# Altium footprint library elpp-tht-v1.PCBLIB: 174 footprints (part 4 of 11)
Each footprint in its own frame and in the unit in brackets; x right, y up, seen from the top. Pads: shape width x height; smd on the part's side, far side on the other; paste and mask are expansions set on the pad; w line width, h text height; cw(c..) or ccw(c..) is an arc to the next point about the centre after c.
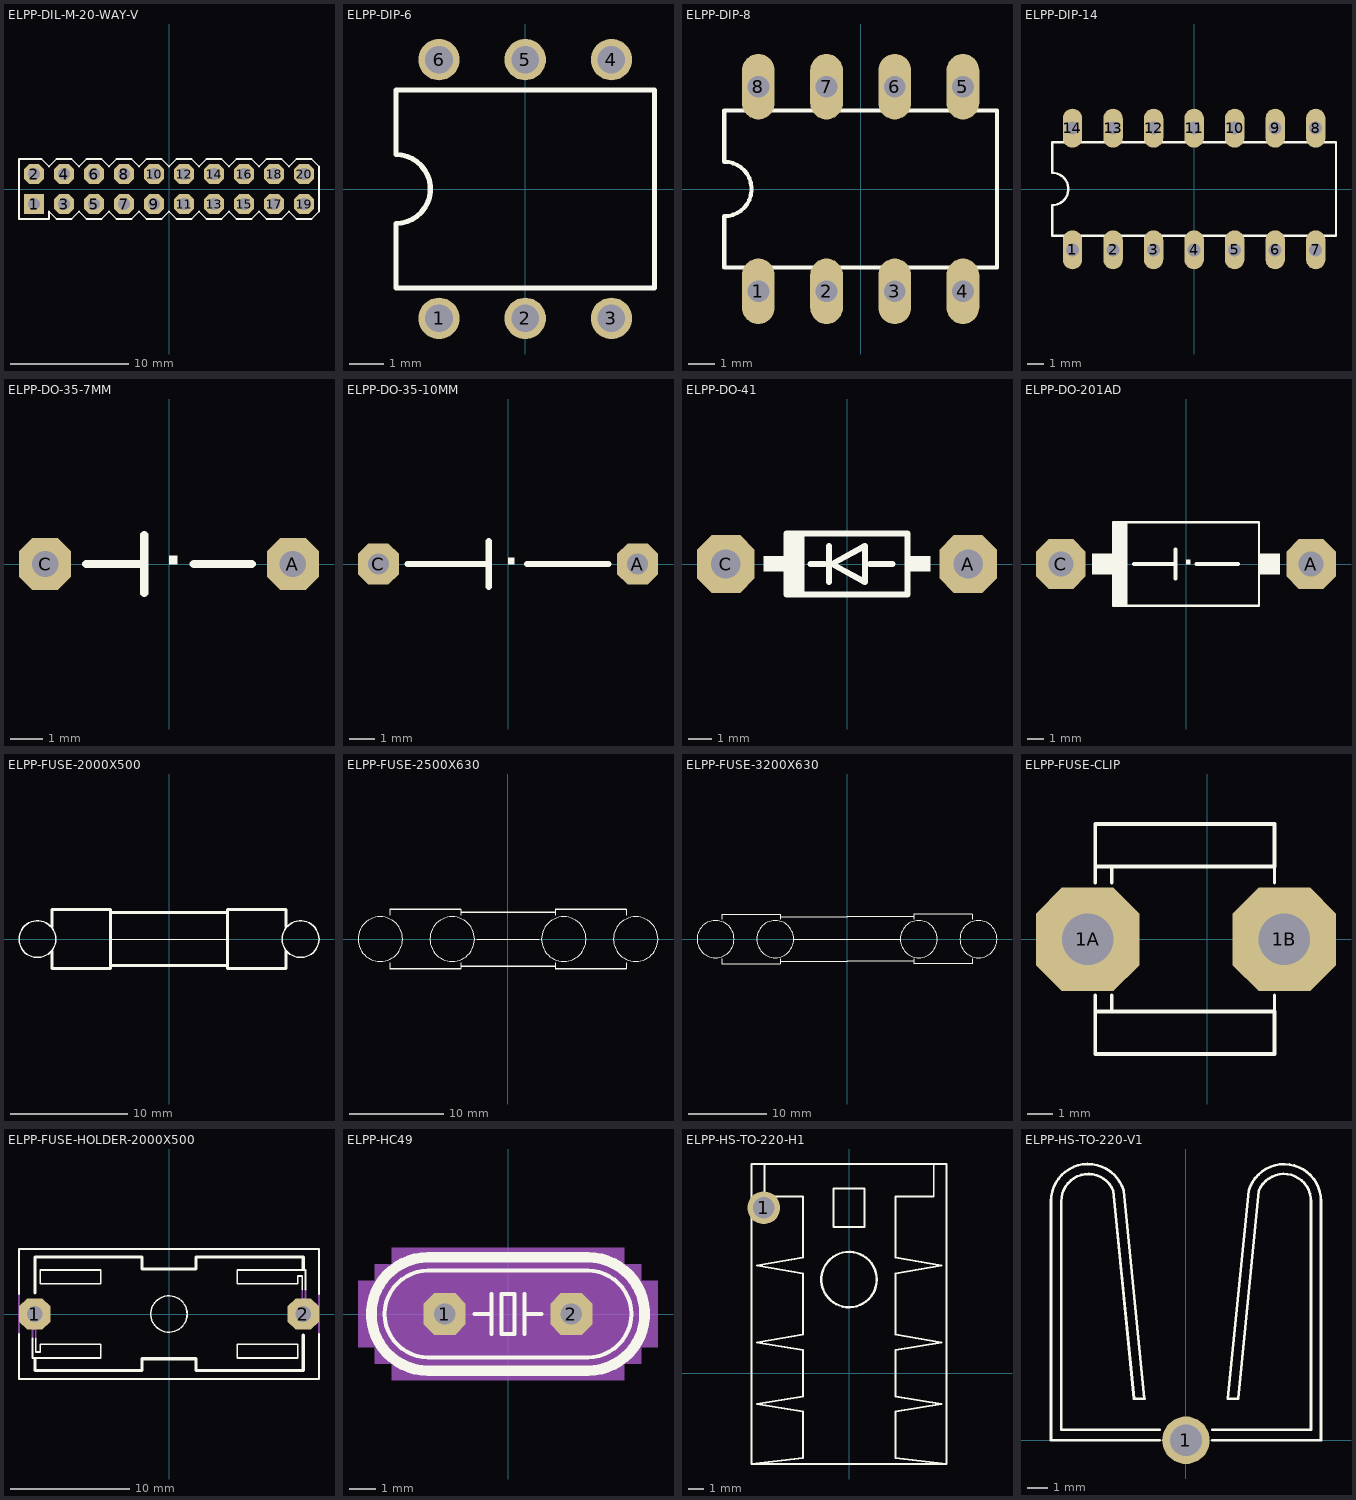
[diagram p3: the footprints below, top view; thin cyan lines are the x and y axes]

## ELPP-DIL-M-20-WAY-V [mil]
pads (20):
  rect 67x67 hole 40: 1(-450,-50)
  oct 67x67 hole 40: 2(-450,50) 3(-350,-50) 4(-350,50) 5(-250,-50) 6(-250,50) 7(-150,-50) 8(-150,50) 9(-50,-50) 10(-50,50) 11(50,-50) 12(50,50) 13(150,-50) 14(150,50) 15(250,-50) 16(250,50) 17(350,-50) 18(350,50) 19(450,-50) 20(450,50)
Top Overlay:
  lines w6: -500,-100 -400,-100 -400,-75 -375,-100 -325,-100 -300,-75 -275,-100 -225,-100 -200,-75 -175,-100 -125,-100 -100,-75 -75,-100 -25,-100 0,-75 25,-100 75,-100 100,-75 125,-100 175,-100 200,-75 225,-100 275,-100 300,-75 325,-100 375,-100 400,-75 425,-100 475,-100 500,-75 500,75 475,100 425,100 400,75 375,100 325,100 300,75 275,100 225,100 200,75 175,100 125,100 100,75 75,100 25,100 0,75 -25,100 -75,100 -100,75 -125,100 -175,100 -200,75 -225,100 -275,100 -300,75 -325,100 -375,100 -400,75 -425,100 -500,100 -500,-100
Mechanical 2:
  text ">NAME" at -500,125 h42.5
Mechanical 4:
  text ">VALUE" at -500,-175 h42.5
Mechanical 16:
  rectangle: -360,-60 -340,-40
  rectangle: -460,-60 -440,-40
  rectangle: -260,-60 -240,-40
  rectangle: -60,-60 -40,-40
  rectangle: -160,-60 -140,-40
  rectangle: 40,-60 60,-40
  rectangle: 140,-60 160,-40
  rectangle: 240,-60 260,-40
  rectangle: 340,-60 360,-40
  rectangle: 440,-60 460,-40
  rectangle: -360,40 -340,60
  rectangle: -460,40 -440,60
  rectangle: -260,40 -240,60
  rectangle: -60,40 -40,60
  rectangle: -160,40 -140,60
  rectangle: 40,40 60,60
  rectangle: 140,40 160,60
  rectangle: 240,40 260,60
  rectangle: 340,40 360,60
  rectangle: 440,40 460,60

## ELPP-DIP-6 [mil]
pads (6):
  round 48 hole 32: 1(-100,-150) 2(0,-150) 3(100,-150) 4(100,150) 5(0,150) 6(-100,150)
Top Overlay:
  lines w6: -150,-115 150,-115 150,115 -150,115 -150,40 cw(c-150,0) -150,-40 -150,-115
Mechanical 2:
  text ">NAME" at -160,-115 h42.5
Mechanical 4:
  text ">VALUE" at -95,-25 h42.5

## ELPP-DIP-8 [mil]
pads (8):
  oval 48x96 hole 32: 1(-150,-150) 2(-50,-150) 3(50,-150) 4(150,-150) 5(150,150) 6(50,150) 7(-50,150) 8(-150,150)
Top Overlay:
  lines w6: -200,-115 200,-115 200,115 -200,115 -200,40 cw(c-200,0) -200,-40 -200,-115
Mechanical 2:
  text ">NAME" at -225,-150 h42.5
Mechanical 4:
  text ">VALUE" at -115,-25 h42.5

## ELPP-DIP-14 [mil]
pads (14):
  oval 48x96 hole 32: 1(-300,-150) 2(-200,-150) 3(-100,-150) 4(0,-150) 5(100,-150) 6(200,-150) 7(300,-150) 8(300,150) 9(200,150) 10(100,150) 11(0,150) 12(-100,150) 13(-200,150) 14(-300,150)
Top Overlay:
  lines w6: -350,-115 350,-115 350,115 -350,115 -350,40 cw(c-350,0) -350,-40 -350,-115
Mechanical 2:
  text ">NAME" at -365,-120 h42.5
Mechanical 4:
  text ">VALUE" at -265,-25 h42.5

## ELPP-DO-35-7MM [mil]
pads (2):
  oct 63x63 hole 32: A(150,0) C(-150,0)
Top Overlay:
  region: 0,0 10,0 10,10 0,10
  lines w10: -100,0 -32.5,0 ; -30,-35 -30,35 ; 30,0 100,0
Mechanical 2:
  text ">NAME" at -100,50 h42.5
Mechanical 4:
  text ">VALUE" at -100,-100 h42.5

## ELPP-DO-35-10MM [mil]
pads (2):
  oct 63x63 hole 32: A(200,0) C(-200,0)
Top Overlay:
  region: 0,0 10,0 10,10 0,10
  lines w10: -155,0 -32.5,0 ; -30,-35 -30,35 ; 30,0 155,0
Mechanical 2:
  text ">NAME" at -100,50 h42.5
Mechanical 4:
  text ">VALUE" at -100,-100 h42.5

## ELPP-DO-41 [mil]
pads (2):
  oct 95x95 hole 48: A(200,0) C(-200,0)
Top Overlay:
  rectangle: -137.5,-12.5 -100,13
  rectangle: 100,-12.5 138,13
  lines w10: -60,0 -37.5,0 ; -30,-30 -30,30 ; 38,0 75,0 ; -95,-50 -100,-50 -100,50 -95,50 ; -95,-50 -90,-50 ; -95,-50 -95,50 ; -95,50 -90,50 ; -90,-50 -85,-50 ; -90,-50 -90,50 ; -90,50 -85,50 ; -85,-50 -75,-50 ; -85,-50 -85,50 ; -85,50 -75,50 ; -75,-50 100,-50 100,50 -75,50 ; -75,-50 -75,50 ; -25,0 30,30 30,-30 -25,0
Mechanical 2:
  text ">NAME" at -100,75 h42.5
Mechanical 4:
  text ">VALUE" at -100,-125 h42.5

## ELPP-DO-201AD [mil]
pads (2):
  oct 119x119 hole 60: A(300,0) C(-300,0)
Top Overlay:
  rectangle: -225,-25 -175,25
  rectangle: 175,-25 225,25
  region: 0,0 10,0 10,10 0,10
  lines w5: -175,-100 -175,100 175,100 175,-100 -175,-100
  lines w10: -170,-95 -170,95 ; -160,-95 -160,95 ; -150,-95 -150,95 ; -145,-95 -145,95 ; -125,0 -37.5,0 ; -95,0 -27.5,0 ; -25,-35 -25,35 ; 25,0 125,0 ; 35,0 105,0
Mechanical 2:
  text ">NAME" at -125,125 h42.5
Mechanical 4:
  text ">VALUE" at -150,-175 h42.5

## ELPP-FUSE-2000X500 [mil]
Top Overlay:
  circle w5: c-443,0 r62
  circle w5: c443,0 r62
  lines w2: -196.85,0 197,0
  lines w10: -393.7,-39.37 -393.7,-98.43 -196.85,-98.43 -196.85,-88.58 ; -393.7,40 -393.7,99 -196.85,99 -196.85,89 ; 394,-39.37 394,-98.43 197,-98.43 197,-88.58 ; 394,40 394,99 197,99 197,89 ; -196.85,-88.58 -196.85,0 -196.85,89 ; -196.85,-88.58 197,-88.58 ; -196.85,89 197,89 ; 197,-88.58 197,0 197,89
Mechanical 2:
  text ">NAME" at -500,250 h42.5
Mechanical 4:
  text ">VALUE" at 1,250 h42.5

## ELPP-FUSE-2500X630 [mil]
Top Overlay:
  circle w5: c-532.2,0 r93
  circle w5: c-232.2,0 r93
  circle w5: c233,0 r93
  circle w5: c533,0 r93
  lines w2: -129.92,0 130,0
  lines w5: -492.13,-124.02 -492.13,-98.43 ; -492.13,99 -492.13,125 ; -196.85,-124.02 -196.85,-112.2 -196.85,-98.43 ; -196.85,99 -196.85,113 -196.85,125 ; 197,-124.02 197,-112.2 197,-98.43 ; 197,99 197,113 197,125 ; 493,-124.02 493,-98.43 ; 493,99 493,125
  lines w6: -492.13,-124.02 -196.85,-124.02 ; -492.13,125 -196.85,125 ; -196.85,-112.2 0,-112.2 197,-112.2 ; -196.85,113 0,113 197,113 ; 197,-124.02 493,-124.02 ; 197,125 493,125
Mechanical 2:
  text ">NAME" at -200,150 h42.5
Mechanical 4:
  text ">VALUE" at -200,-200 h42.5

## ELPP-FUSE-3200X630 [mil]
Top Overlay:
  circle w5: c-660,0 r93
  circle w5: c-360,0 r93
  circle w5: c360,0 r93
  circle w5: c660,0 r93
  lines w2: -267.72,0 268,0
  lines w5: -629.92,-124.02 -629.92,-98.43 ; -629.92,99 -629.92,125 ; -334.65,-124.02 -334.65,-112.2 -334.65,-98.43 ; -334.65,99 -334.65,113 -334.65,125 ; 335,-124.02 335,-112.2 335,-98.43 ; 335,99 335,113 335,125 ; 630,-124.02 630,-98.43 ; 630,99 630,125
  lines w6: -629.92,-124.02 -334.65,-124.02 ; -629.92,125 -334.65,125 ; -334.65,-112.2 0,-112.2 335,-112.2 ; -334.65,113 0,113 335,113 ; 335,-124.02 630,-124.02 ; 335,125 630,125
Mechanical 2:
  text ">NAME" at -200,150 h42.5
Mechanical 4:
  text ">VALUE" at -200,-200 h42.5

## ELPP-FUSE-CLIP [mil]
pads (2):
  oct 158x158 hole 79: 1A(-182.2,0) 1B(118,0)
Top Overlay:
  lines w5: -170.71,-109.91 -170.71,-84.91 ; -170.71,86 -170.71,111 ; -145.71,-109.91 -145.71,-84.91 ; -145.71,86 -145.71,111 ; 103,-109.91 103,-84.91 ; 103,86 103,111
  lines w6: -170.71,-174.91 103,-174.91 103,-149.91 103,-109.91 -145.71,-109.91 -152.09,-109.91 -170.71,-109.91 -170.71,-174.91 ; -170.71,111 -145.71,111 103,111 103,151 103,176 -170.71,176 -170.71,111
Mechanical 2:
  text ">NAME" at -158.9,206 h42.5
Mechanical 4:
  text ">VALUE" at -158.9,-234.91 h42.5

## ELPP-FUSE-HOLDER-2000X500 [mil]
pads (2):
  oct 103x103 hole 52: 1(-443,0) 2(443,0)
Top Overlay:
  circle w5: c0,0 r60
  lines w6: -495,-65 -495,-215 495,-215 495,-65 ; -495,65 -495,215 495,215 495,65 ; -450,-80 -450,-145 -425,-145 -225,-145 -225,-100 -425,-100 -425,-125 -440,-125 -440,-80 ; 440,80 440,125 425,125 425,100 225,100 225,145 425,145 450,145 450,80 ; -425,100 -425,145 -225,145 -225,100 -425,100 ; 225,-145 425,-145 425,-100 225,-100 225,-145
  lines w10: -442.91,-147.64 -442.91,-187.01 -88.58,-187.01 -88.58,-147.64 89,-147.64 89,-187.01 443,-187.01 443,-68.9 ; -442.91,69 -442.91,188 -88.58,188 -88.58,148 89,148 89,188 443,188 443,148
Mechanical 2:
  text ">NAME" at -500,-300 h42.5
Mechanical 4:
  text ">VALUE" at 1,-300 h42.5
Mechanical 16:
  lines w6: -495,-65 -495,65 ; -450,-80 -450,-50 -440,-50 -440,-80 ; 440,80 440,50 450,50 450,80 ; 495,-65 495,65

## ELPP-HC49 [mil]
pads (2):
  oct 63x63 hole 32: 1(-95,0) 2(95,0)
Top Overlay:
  lines w6: -50,0 -25,0 ; -25,-30 -25,0 ; -25,30 -25,0 ; 25,-30 25,0 ; 25,30 25,0 ; 50,0 25,0 ; -120,-65 120,-65 ccw(c120,0) 120,65 -120,65 ccw(c-120,0) -120,-65 ; -10,-30 10,-30 10,30 -10,30 -10,-30
  lines w16: -120,-85 120,-85 ccw(c120,0) 120,85 -120,85 ccw(c-120,0) -120,-85
Mechanical 2:
  text ">NAME" at -200,105 h42.5
Mechanical 4:
  text ">VALUE" at -200,-155 h42.5
Mechanical 10:
  rectangle: -175,-100 175,100
  rectangle: -200,-75 -175,75
  rectangle: -225,-50 -200,50
  rectangle: 175,-75 200,75
  rectangle: 200,-50 225,50

## ELPP-HS-TO-220-H1 [mil]
pads (1):
  round 84 hole 56: 1(-218.5,424)
Top Overlay:
  circle w6: c0,240 r71
  lines w5: -216.54,532 -216.54,453 -118.11,453 -118.11,296 -236.22,276 -118.11,256 -118.11,99 -236.22,79 -118.11,60 -118.11,-59.06 -236.22,-78.74 -118.11,-98.43 -118.11,-216.54 -250,-232.44 ; 217,532 217,453 119,453 119,296 237,276 119,256 119,99 237,79 119,60 119,-59.06 237,-78.74 119,-98.43 119,-216.54 250,-232.44 ; -250,-232.44 -250,536 250,536 250,-232.44 ; -250,-232.44 250,-232.44 ; -39.37,375 40,375 40,473 -39.37,473 -39.37,375
Mechanical 2:
  text ">NAME" at -274.06,-222.52 h42.5
Mechanical 4:
  text ">VALUE" at 350,-227.52 h42.5

## ELPP-HS-TO-220-V1 [mil]
pads (1):
  round 90 hole 60: 1(0,0)
Top Overlay:
  lines w5: -50,0 -255.91,0 -255.91,453 cw(c-185.61,453.35) -118.11,473 -78.74,79 -98.43,79 -137.8,473 ccw(c-185.08,453.52) -236.22,453 -236.22,20 -50,20 ; 50,0 256,0 256,453 ccw(c186.1,453.41) 119,473 79,79 99,79 138,473 cw(c185.57,453.47) 237,453 237,20 50,20
Mechanical 2:
  text ">NAME" at -275.59,0 h42.5
Mechanical 4:
  text ">VALUE" at 335,0 h42.5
